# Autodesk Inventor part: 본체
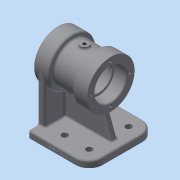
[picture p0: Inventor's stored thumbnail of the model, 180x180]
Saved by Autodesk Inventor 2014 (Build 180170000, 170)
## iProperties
Created: 2020-06
Part Number: 본체
Material: Generic
Document SubType Name: Modeling
Designer: kh
Density: 1 g/cm^3
Appearance: Default
Author: kh
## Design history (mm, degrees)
sketch "Sketch1"
  geometry: L1 (45, -49)-(-45, -49); L2 (-45, -49)-(-45, 49); L3 (-45, 49)-(45, 49); L4 (45, 49)-(45, -49); L5 (45, -49)-(-45, 49); L6 (-45, -49)-(45, 49); 1 further point
  constraints: 12 end point, 2 midpoint, 2 parallel, 1 horizontal, 1 perpendicular
  dimensions: "d0" = 90 distance between parallel lines of L2 L4; "d1" = 98 distance between parallel lines of L3 L1
extrude "Extrusion1" new body sketch "Sketch1" distance "d2" = 10; taper "d3" = 0 deg
sketch "Sketch3"
  geometry: L1 (45, 0)-(45, -10) reference; L2 (45, -10)-(-45, -10) reference; L3 (-45, -10)-(-45, 0) reference; L4 (-45, 0)-(45, 0) reference; L5 (45, 0)-(-45, 0) reference; L6 (45, 0)-(45, -10) reference; L7 (45, -10)-(-45, -10) reference; L8 (-45, -10)-(-45, 0) reference; L9 (-45, 0)-(45, 0) reference; L10 (-61.724, 70)-(61.724, 70); L11 (-50, 70)-(-50, 105); L12 (-50, 105)-(-28, 105); L13 (-28, 105)-(-28, 99); L14 (-28, 99)-(6, 99); L15 (6, 99)-(6, 105); L16 (6, 105)-(28, 105); L17 (28, 105)-(28, 70); 5 further points
  constraints: 16 end point, 4 midpoint, 4 parallel, 2 point on line, 1 collinear, 1 perpendicular, 1 vertical alignment
  dimensions: "d16" = 35 distance of L11.start L11.end; "d17" = 22 distance of L11.end L12.end; "d19" = 34 distance of L13.end L14.end; "d21" = 22 distance of L15.end L16.end; "d22" = 35 distance of L16.end L17.end; "d46" = 80 distance from line of L2 point (0, 70); "d47" = 58 diameter of L14 L10
revolve "Revolution1" sketch "Sketch3" stored, may be unused: angle "d12" = 90 deg
sketch "Sketch6"
  geometry: L1 (45, 0)-(45, -10) reference; L2 (45, -10)-(-45, -10) reference; L3 (-45, -10)-(-45, 0) reference; L4 (-45, 0)-(45, 0) reference; L5 (-50, 35)-(-50, 105) reference; L6 (-50, 105)-(-28, 105) reference; L7 (-28, 105)-(-28, 99) reference; L8 (-28, 99)-(6, 99) reference; L9 (6, 99)-(6, 105) reference; L10 (6, 105)-(28, 105) reference; L11 (28, 105)-(28, 35) reference; L12 (28, 35)-(6, 35) reference; L13 (6, 35)-(6, 41) reference; L14 (6, 41)-(-28, 41) reference; L15 (-28, 41)-(-28, 35) reference; L16 (-28, 35)-(-50, 35) reference; L17 (-45, 0)-(-45, 70); L18 (-45, 70)-(-35, 70); L19 (-35, 70)-(-35, 0); 1 further point
  constraints: 6 end point, 2 perpendicular, 1 parallel, 1 point on line
  dimensions: "d24" = 10 distance of L17.end L18.end; "d35" = 70 distance between parallel lines of L4 L18
extrude "Extrusion2" join sketch "Sketch6" stored distance "d25" = 70; taper "d26" = 0 deg
sketch "Sketch7"
  geometry: L1 (12.753, 55.628)-(33, 0); L2 (45, 0)-(45, -10) reference; L3 (45, -10)-(-45, -10) reference; L4 (-45, -10)-(-45, 35) reference; L5 (-45, 35)-(-50, 35) reference; L6 (-50, 35)-(-50, 105) reference; L7 (-50, 105)-(-28, 105) reference; L8 (-28, 105)-(-28, 99) reference; L9 (-28, 99)-(6, 99) reference; L10 (6, 99)-(6, 105) reference; L11 (6, 105)-(28, 105) reference; L12 (28, 105)-(28, 35) reference; L13 (28, 35)-(6, 35) reference; L14 (6, 35)-(6, 41) reference; L15 (6, 41)-(-28, 41) reference; L16 (-28, 41)-(-28, 35) reference; L17 (-28, 35)-(-35, 35) reference; L18 (-35, 35)-(-35, 0) reference; L19 (-35, 0)-(45, 0) reference; 1 further point
  constraints: 2 end point, 1 point on line
  dimensions: "d27" = 70 deg angle of L19 L1; "d28" = 12 distance of L2.start L1.end
feature "Rib1" sketch "Sketch7" dims "d29" = 1, "d30" = 10, "d31" = 0, "d32" = 0, "d33" = 1, "d34" = 1
sketch "Sketch8"
  geometry: L1 (45, -10)-(-45, -10) reference; L2 (-45, -10)-(-45, 35) reference; L3 (-45, 35)-(-50, 35) reference; L4 (-50, 35)-(-50, 105) reference; L5 (-50, 105)-(-28, 105) reference; L6 (-28, 105)-(-28, 99) reference; L7 (-28, 99)-(6, 99) reference; L8 (6, 99)-(6, 105) reference; L9 (6, 105)-(28, 105) reference; L10 (28, 105)-(28, 35) reference; L11 (28, 35)-(20.261, 35) reference; L12 (20.261, 35)-(33, 0) reference; L13 (33, 0)-(45, 0) reference; L14 (45, 0)-(45, -10) reference; L15 (-50, 70)-(28, 70); L16 (-50, 70)-(-50, 93.5); L17 (-50, 93.5)-(-32, 93.5); L18 (-32, 93.5)-(-32, 90); L19 (-32, 90)-(-26, 90); L20 (-26, 90)-(-26, 93); L21 (-26, 93)-(4, 93); L22 (4, 93)-(4, 90); L23 (4, 90)-(10, 90); L24 (10, 90)-(10, 93.5); L25 (10, 93.5)-(28, 93.5); L26 (28, 70)-(28, 93.5); 1 further point
  constraints: 24 end point, 6 perpendicular, 3 parallel, 2 midpoint, 2 point on line, 1 collinear
  dimensions: "d36" = 23.5 distance of L15.start L16.end; "d37" = 18 distance of L16.end L17.end; "d39" = 6 distance of L18.end L19.end; "d41" = 30 distance of L20.end L21.end; "d43" = 6 distance of L22.end L23.end; "d108" = 46 diameter of L21 L15; "d110" = 47 diameter of L25 L15; "d114" = 40 diameter of L23 L15; "d115" = 40 diameter of L19 L15
revolve "Revolution2" sketch "Sketch8" stored, may be unused: angle "d45" = 90 deg
workplane "Work Plane1"
sketch "Sketch9"
  geometry: L1 (6, -14.177)-(6, 14.177) reference; L2 (6, 14.177)-(28, 14.177) reference; L3 (28, 14.177)-(28, -14.177) reference; L4 (28, -14.177)-(6, -14.177) reference; L5 (-28, 14.177)-(-28, -14.177) reference; L6 (-28, -14.177)-(-50, -14.177) reference; L7 (-50, -14.177)-(-50, 14.177) reference; L8 (-50, 14.177)-(-28, 14.177) reference; C1 r 6 at (-11, 0); 1 further point
  constraints: 1 centre point
  dimensions: "d49" = 12 diameter of C1; "d50" = 39 distance from line of C1.centre L7
extrude "Extrusion3" join sketch "Sketch9" stored distance "d51" = 70; taper "d52" = 0 deg
hole "Hole1" diameter "d55" = 5.188; stored, may be unused: countersink angle "d59" = 90 deg, drill point angle "d61" = 118 deg; dims "d56" = 6, "d57" = 4, "d58" = 2, "d60" = 15, "d111" = 10, "d112" = 10
sketch "Sketch10"
  geometry: C1 r 23.5 at (0, 0) reference; 2 further points
  constraints: 1 vertical alignment
  dimensions: "d64" = 28.5 distance of C1.centre point (0, 28.5)
hole "Hole2" sketch "Sketch10" at (0, 28.5) diameter "d65" = 3.459; stored, may be unused: countersink angle "d69" = 90 deg, drill point angle "d71" = 118 deg; dims "d66" = 10, "d67" = 4, "d68" = 2, "d70" = 12
pattern_circular "Circular Pattern1" dims angle "d73" = 360 deg
workplane "Work Plane2"
mirror "Mirror1"
fillet "Fillet1" dims "d75" = 20
hole "Hole3" diameter "d78" = 9; stored, may be unused: countersink angle "d82" = 90 deg, drill point angle "d84" = 118 deg; dims "d76" = 10, "d77" = 10, "d79" = 10, "d80" = 4, "d81" = 2, "d83" = 12
pattern_linear "Rectangular Pattern1" dims "d89" = 36
fillet "Fillet2" dims "d90" = 3
fillet "Fillet3" dims "d91" = 3
fillet "Fillet4" dims "d92" = 3
fillet "Fillet5" dims "d93" = 3
fillet "Fillet6" dims "d94" = 3
chamfer "Chamfer1" distance "d95" = 1; stored, may be unused: second distance "d96" = 2, angle "d97" = 45 deg
chamfer "Chamfer2" distance "d98" = 1; stored, may be unused: second distance "d99" = 2, angle "d100" = 45 deg
fillet "Fillet7" dims "d101" = 0.3
sketch "Sketch11"
  geometry: L1 (0, 0)-(-67, 0) reference; L2 (0, 0)-(-67, 0) reference; L3 (-67, 7)-(-67, 0) reference; L4 (0, 7)-(-67, 7) reference; L5 (0, 7)-(0, 0) reference; L6 (-70, 7)-(-70, 0) reference; 2 further points
  constraints: 1 other
  dimensions: "d102" = 4 distance from line of L1 point (-25, 4); "d103" = 45 distance from line of L6 point (-25, 4)
emboss "Emboss1" sketch "Sketch11" dims "d0" = 90, "d1" = 98, "d16" = 35, "d17" = 22, "d19" = 34, "d21" = 22, "d22" = 35, "d46" = 80, "d47" = 58, "d104" = 0.5, "d105" = 0
fillet "Fillet8" dims "d113" = 3
body "Solid1"
node "Project Cut Edges1"
node "Project Cut Edges2"
node "Project Cut Edges3"
node "Project Cut Edges4"
node "Project Cut Edges5"
node "Project Cut Edges6"
node "Project Cut Edges7"
other parameters: "d48" = 102
